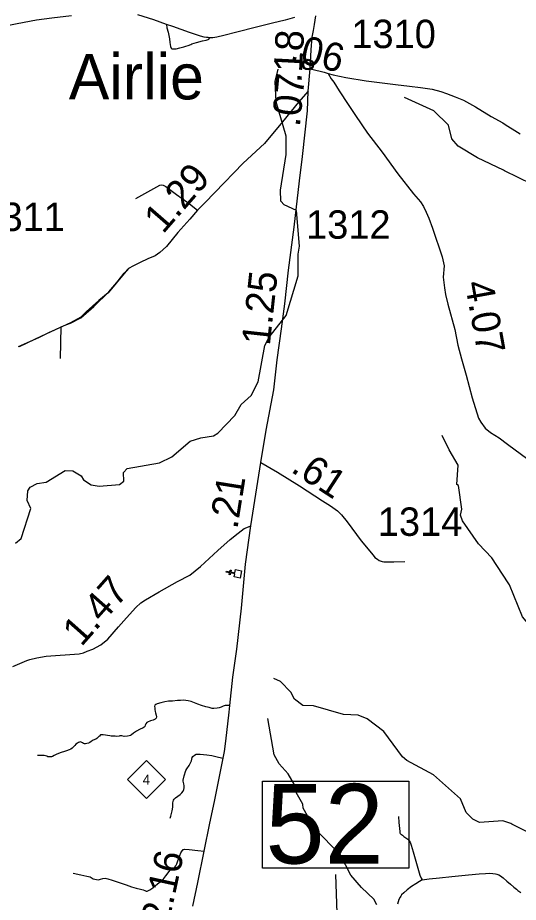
# Model space of a CAD drawing. Extents: x 2290615 to 2522933, y 819489 to 1012715.
# Drawn here: x 2322940 to 2331750, y 928394 to 943964 of the extents above; entities that cross this region are included whole.
import ezdxf

# ---------------------------------------------------------------- set-up
doc = ezdxf.new("R2010")
doc.units = 0
for name, color, linetype in [('Exist Civil Demographics City Label', 7, 'Continuous'), ('Exist Civil Demographics Community CELL', 7, 'Continuous'), ('Exist Cultural Church CELL', 7, 'Continuous'), ('Exist Hydrographic Misc Water Feature', 7, 'Continuous'), ('Exist Road Non-System Type 51', 7, 'Continuous'), ('Exist Road Primary NC Attributed', 7, 'Continuous'), ('Exist Road Primary NC Mileage Hundredths English Label', 7, 'Continuous'), ('Exist Road Primary NC Shield CELL', 7, 'Continuous'), ('Exist Road Primary NC Shield Number Label', 7, 'Continuous'), ('Exist Road Primary NC Structure Standard Bridge Number Label', 7, 'Continuous'), ('Exist Road Secondary Mileage Hundredths English Label', 7, 'Continuous'), ('Exist Road Secondary Type 20 Attributed', 7, 'Continuous'), ('Exist Road Secondary Type 41 Attributed', 7, 'Continuous'), ('Exist Road Secondary Type 51 Attributed', 7, 'Continuous'), ('Exist Road Secondary Type 51 Number Label', 7, 'Continuous')]:
    doc.layers.add(name, color=color, linetype=linetype)

msp = doc.modelspace()

# ---------------------------------------------------------------- linework, layer by layer
at = {"layer": 'Exist Civil Demographics Community CELL'}
msp.add_lwpolyline([(2327972, 943150), (2327973, 943156), (2327975, 943162), (2327978, 943169), (2327981, 943175), (2327984, 943181), (2327988, 943186), (2327992, 943190), (2327996, 943195), (2328002, 943200), (2328007, 943203), (2328012, 943206), (2328017, 943209), (2328023, 943211), (2328028, 943213), (2328033, 943214), (2328037, 943215), (2328042, 943215), (2328048, 943216), (2328052, 943215), (2328058, 943215), (2328063, 943214), (2328068, 943213), (2328073, 943212), (2328078, 943210), (2328085, 943207), (2328091, 943204), (2328096, 943200), (2328101, 943196), (2328104, 943193), (2328109, 943189), (2328112, 943184), (2328116, 943179), (2328119, 943174), (2328121, 943169), (2328123, 943164), (2328125, 943159), (2328126, 943155), (2328127, 943148), (2328128, 943144), (2328128, 943138), (2328128, 943132), (2328127, 943126), (2328126, 943121), (2328125, 943115), (2328123, 943109), (2328120, 943104), (2328117, 943098), (2328114, 943092), (2328111, 943088), (2328106, 943083), (2328101, 943078), (2328096, 943074), (2328091, 943070), (2328087, 943068), (2328080, 943065), (2328073, 943062), (2328067, 943061), (2328060, 943059), (2328056, 943059), (2328051, 943059), (2328046, 943059), (2328041, 943059), (2328036, 943060), (2328030, 943061), (2328025, 943062), (2328020, 943064), (2328016, 943066), (2328012, 943068), (2328005, 943072), (2327999, 943077), (2327994, 943081), (2327990, 943086), (2327987, 943090), (2327984, 943094), (2327980, 943101), (2327978, 943105), (2327976, 943109), (2327974, 943117), (2327972, 943124), (2327971, 943129), (2327971, 943136), (2327971, 943140), (2327971, 943147)], close=True, dxfattribs=at)
for centre, radius in [((2328050, 943138), 94.3), ((2328049, 943138), 76.7)]:
    msp.add_circle(centre, radius, dxfattribs=at)
at = {"layer": 'Exist Cultural Church CELL'}
msp.add_lwpolyline([(2326749, 934122), (2326760, 934178), (2326685, 934192), (2326679, 934161), (2326663, 934164), (2326669, 934195), (2326610, 934207), (2326613, 934223), (2326672, 934211), (2326679, 934242), (2326694, 934239), (2326688, 934208), (2326763, 934193), (2326774, 934250), (2326879, 934230), (2326854, 934101)], close=True, dxfattribs=at)
at = {"layer": 'Exist Hydrographic Misc Water Feature'}
for points in [[(2322900, 934714), (2323000, 934797), (2323169, 935323), (2323109, 935464), (2323116, 935639), (2323157, 935700), (2323281, 935767), (2323439, 935787), (2323778, 935997), (2323912, 935990), (2324054, 935900), (2324096, 935833), (2324231, 935744), (2324373, 935720), (2324731, 935748), (2324805, 935807), (2324803, 935958), (2324869, 936032), (2325434, 936131), (2325650, 936235), (2325972, 936511), (2326163, 936571), (2326387, 936607), (2326462, 936649), (2326759, 936964), (2326873, 937155), (2327046, 937317), (2327169, 937558), (2327287, 938193), (2327368, 938344), (2327664, 938721), (2327873, 939422), (2327878, 939800), (2327901, 939942), (2327844, 940573), (2327627, 940669), (2327568, 940735), (2327565, 940929), (2327667, 941554), (2327664, 941878), (2327491, 942485), (2327470, 942842), (2327526, 943061)], [(2331507, 941268), (2331488, 941278), (2331033, 941498), (2330690, 941704), (2330580, 941834), (2330519, 942075), (2330266, 942324), (2329747, 942558)], [(2334376, 940329), (2333833, 940465), (2333313, 940742), (2333146, 940787), (2332887, 940826), (2332727, 940918), (2332227, 940953), (2331985, 941032), (2331507, 941268)], [(2331594, 933982), (2331571, 934018), (2331284, 934455), (2331048, 934701), (2330769, 935106), (2330734, 935207), (2330758, 935313), (2330695, 935730), (2330670, 935746), (2330692, 936088), (2330531, 936360), (2330411, 936611)], [(2334475, 930033), (2334441, 930065), (2334439, 930242), (2334471, 930282), (2334469, 930483), (2334392, 930630), (2334296, 930997), (2334110, 931229), (2333638, 931679), (2333571, 931778), (2332900, 932105), (2332757, 932254), (2332646, 932476), (2332266, 932847), (2332215, 932996), (2332121, 933127), (2331978, 933236), (2331826, 933417), (2331594, 933982)], [(2331637, 929772), (2331619, 929779), (2331475, 929831), (2331067, 929801), (2330950, 929859), (2330832, 929975), (2330730, 930214), (2330259, 930635), (2329789, 930888), (2329714, 930953), (2329384, 931399), (2329090, 931624), (2328931, 931686), (2328673, 931702), (2328146, 931854), (2327955, 931859), (2327812, 931968), (2327744, 932090), (2327567, 932280), (2327450, 932331)], [(2329258, 928352), (2329207, 928448), (2328989, 928656), (2328803, 928871), (2328616, 929234), (2328170, 929689), (2327966, 930051), (2327957, 930120), (2327838, 930325), (2327803, 930474), (2327701, 930657), (2327541, 930831), (2327456, 930989), (2327341, 931627)], [(2333816, 928683), (2333772, 928875), (2333712, 928974), (2333595, 929071), (2333218, 929233), (2333041, 929400), (2332856, 929504), (2331905, 929635), (2331637, 929772)]]:
    msp.add_lwpolyline(points, dxfattribs=at)
at = {"layer": 'Exist Road Non-System Type 51'}
msp.add_line((2323691, 937966), (2323707, 938526), dxfattribs=at)
msp.add_line((2323691, 937966), (2323707, 938526), dxfattribs=at)
for points in [[(2325561, 943844), (2325563, 943783), (2325587, 943708), (2325612, 943595), (2325617, 943526), (2325630, 943459), (2325640, 943429), (2325651, 943417), (2325674, 943415), (2325729, 943419), (2325793, 943433), (2325863, 943452), (2325899, 943464), (2325942, 943475), (2325986, 943492), (2326003, 943502), (2326089, 943528), (2326190, 943555), (2326257, 943568), (2326290, 943579), (2326306, 943589), (2326321, 943608)], [(2325561, 943844), (2325563, 943783), (2325587, 943708), (2325612, 943595), (2325617, 943526), (2325630, 943459), (2325640, 943429), (2325651, 943417), (2325674, 943415), (2325729, 943419), (2325793, 943433), (2325863, 943452), (2325899, 943464), (2325942, 943475), (2325986, 943492), (2326003, 943502), (2326089, 943528), (2326190, 943555), (2326257, 943568), (2326290, 943579), (2326306, 943589), (2326321, 943608)], [(2325018, 940784), (2325439, 941014), (2325467, 941022), (2325499, 941019), (2325546, 940991), (2325733, 940853), (2325932, 940713), (2326104, 940576)], [(2325018, 940784), (2325439, 941014), (2325467, 941022), (2325499, 941019), (2325546, 940991), (2325733, 940853), (2325932, 940713), (2326104, 940576)], [(2323707, 938526), (2323784, 938556), (2323871, 938588), (2324049, 938680), (2324282, 938881), (2324542, 939137), (2324684, 939303), (2324815, 939470), (2324890, 939549)], [(2323707, 938526), (2323784, 938556), (2323871, 938588), (2324049, 938680), (2324282, 938881), (2324542, 939137), (2324684, 939303), (2324815, 939470), (2324890, 939549)], [(2322955, 938178), (2323312, 938337), (2323501, 938429), (2323593, 938471), (2323707, 938526)], [(2322955, 938178), (2323312, 938337), (2323501, 938429), (2323593, 938471), (2323707, 938526)], [(2326673, 931860), (2326619, 931860), (2326588, 931859), (2326555, 931846), (2326523, 931830), (2326487, 931819), (2326450, 931809), (2326394, 931805), (2326361, 931807), (2326312, 931821), (2326250, 931834), (2326174, 931857), (2326110, 931882), (2325990, 931930), (2325940, 931939), (2325899, 931946), (2325851, 931950), (2325803, 931948), (2325750, 931946), (2325664, 931937), (2325595, 931932), (2325531, 931921), (2325456, 931905), (2325394, 931887), (2325369, 931875), (2325355, 931862), (2325348, 931841), (2325351, 931819), (2325353, 931786), (2325357, 931754), (2325365, 931732), (2325378, 931691), (2325383, 931659), (2325376, 931634), (2325358, 931620), (2325323, 931602), (2325278, 931591), (2325226, 931567), (2325210, 931558), (2325193, 931534), (2325185, 931511), (2325175, 931490), (2325164, 931477), (2325145, 931467), (2325084, 931438), (2325031, 931406), (2324979, 931371), (2324945, 931342), (2324924, 931332), (2324903, 931327), (2324874, 931320), (2324813, 931315), (2324774, 931324), (2324740, 931324), (2324724, 931317), (2324687, 931314), (2324655, 931316), (2324642, 931317), (2324614, 931317), (2324595, 931319), (2324585, 931321), (2324559, 931324), (2324520, 931333), (2324482, 931338), (2324441, 931340), (2324416, 931344), (2324399, 931342), (2324390, 931335), (2324377, 931321), (2324368, 931312), (2324354, 931299), (2324341, 931286), (2324333, 931278), (2324314, 931268), (2324269, 931249), (2324235, 931226), (2324210, 931207), (2324183, 931198), (2324158, 931187), (2324133, 931184), (2324113, 931185), (2324096, 931192), (2324082, 931200), (2324070, 931207), (2324056, 931214), (2324044, 931217), (2324029, 931215), (2324012, 931207), (2323993, 931194), (2323964, 931176), (2323943, 931156), (2323922, 931132), (2323910, 931118), (2323899, 931105), (2323877, 931088), (2323848, 931077), (2323801, 931062), (2323761, 931048), (2323704, 931032), (2323659, 931014)], [(2323659, 931014), (2323619, 930994), (2323583, 930976), (2323555, 930961), (2323532, 930955), (2323510, 930953), (2323497, 930953), (2323472, 930955), (2323450, 930966), (2323431, 930973), (2323404, 930979), (2323378, 930981), (2323353, 930981), (2323291, 930980)], [(2325625, 929876), (2325635, 929908), (2325660, 930005), (2325667, 930067), (2325668, 930121), (2325672, 930145), (2325674, 930167), (2325684, 930193), (2325694, 930211), (2325715, 930233), (2325755, 930261), (2325797, 930290), (2325830, 930322), (2325854, 930351), (2325864, 930381), (2325867, 930412), (2325867, 930446), (2325861, 930480), (2325852, 930526), (2325854, 930544), (2325871, 930623), (2325897, 930717), (2325915, 930744), (2325957, 930801), (2325997, 930883), (2326008, 930942), (2326020, 930960), (2326051, 930985), (2326079, 930999), (2326115, 931003), (2326153, 931000), (2326266, 930987), (2326359, 930976), (2326471, 930951), (2326558, 930934)], [(2329639, 929907), (2329650, 929797), (2329656, 929692), (2329663, 929641), (2329667, 929615), (2329671, 929605), (2329680, 929596), (2329693, 929585), (2329710, 929575), (2329737, 929554), (2329769, 929528), (2329803, 929505), (2329822, 929485), (2329846, 929451), (2329867, 929400), (2329897, 929285), (2329944, 929119), (2329980, 928993), (2330018, 928874), (2330040, 928822), (2330057, 928790)], [(2323916, 928906), (2324049, 928877), (2324155, 928855), (2324216, 928840), (2324270, 928805), (2324325, 928793), (2324359, 928791), (2324398, 928799), (2324439, 928815), (2324479, 928817), (2324526, 928808), (2324605, 928783), (2324707, 928748), (2324850, 928702), (2324943, 928669), (2325027, 928645), (2325102, 928623), (2325148, 928611), (2325177, 928600), (2325203, 928592), (2325217, 928592), (2325268, 928612), (2325320, 928651), (2325400, 928719), (2325469, 928772), (2325513, 928814), (2325544, 928859), (2325568, 928889), (2325599, 928933), (2325630, 928968), (2325665, 928988), (2325692, 929001), (2325705, 929012), (2325720, 929034), (2325740, 929071), (2325760, 929122), (2325793, 929221), (2325813, 929263), (2325835, 929299), (2325853, 929321), (2325862, 929325), (2325880, 929331), (2325958, 929321), (2326111, 929306), (2326223, 929297)], [(2323916, 928906), (2324049, 928877), (2324155, 928855), (2324216, 928840), (2324270, 928805), (2324325, 928793), (2324359, 928791), (2324398, 928799), (2324439, 928815), (2324479, 928817), (2324526, 928808), (2324605, 928783), (2324707, 928748), (2324850, 928702), (2324943, 928669), (2325027, 928645), (2325102, 928623), (2325148, 928611), (2325177, 928600), (2325203, 928592), (2325217, 928592), (2325268, 928612), (2325320, 928651), (2325400, 928719), (2325469, 928772), (2325513, 928814), (2325544, 928859), (2325568, 928889), (2325599, 928933), (2325630, 928968), (2325665, 928988), (2325692, 929001), (2325705, 929012), (2325720, 929034), (2325740, 929071), (2325760, 929122), (2325793, 929221), (2325813, 929263), (2325835, 929299), (2325853, 929321), (2325862, 929325), (2325880, 929331), (2325958, 929321), (2326111, 929306), (2326223, 929297)], [(2330057, 928790), (2330010, 928761), (2329944, 928722), (2329871, 928671), (2329795, 928611), (2329733, 928562), (2329695, 928526), (2329682, 928505), (2329669, 928484), (2329648, 928445), (2329622, 928360)], [(2330057, 928790), (2330097, 928798), (2330182, 928809), (2330364, 928826), (2330579, 928847), (2330871, 928879), (2331058, 928896), (2331171, 928902), (2331250, 928909), (2331299, 928904), (2331348, 928898), (2331371, 928892), (2331405, 928879), (2331439, 928858), (2331484, 928826), (2331546, 928768), (2331610, 928713), (2331672, 928659), (2331716, 928625), (2331742, 928604), (2331792, 928568)]]:
    msp.add_lwpolyline(points, dxfattribs=at)
at = {"layer": 'Exist Road Primary NC Attributed'}
for p, q in [((2328049, 942672), (2328089, 943065)), ((2327042, 935022), (2327220, 936138))]:
    msp.add_line(p, q, dxfattribs=at)
for points in [[(2328089, 943065), (2328106, 943398), (2328124, 943624), (2328145, 943740), (2328164, 943844), (2328186, 944000)], [(2327220, 936138), (2327310, 936705), (2327446, 937413), (2327508, 937942), (2327585, 938489), (2327640, 938926), (2327704, 939520), (2327804, 940277), (2327900, 941095), (2327950, 941522), (2328039, 942325), (2328049, 942672)], [(2326021, 928328), (2326107, 928743), (2326223, 929297), (2326319, 929790), (2326402, 930169), (2326558, 930934), (2326577, 931047), (2326600, 931232), (2326661, 931741), (2326673, 931860), (2326725, 932357), (2326795, 932848), (2326880, 933573), (2326951, 934343), (2327042, 935022)]]:
    msp.add_lwpolyline(points, dxfattribs=at)
at = {"layer": 'Exist Road Primary NC Shield CELL'}
msp.add_lwpolyline([(2324875, 930556), (2325208, 930889), (2325541, 930556), (2325208, 930223)], close=True, dxfattribs=at)
at = {"layer": 'Exist Road Primary NC Structure Standard Bridge Number Label'}
msp.add_line((2328754, 922140), (2328538, 928881), dxfattribs=at)
msp.add_lwpolyline([(2327249, 930527), (2329826, 930527), (2329826, 928998), (2327249, 928998)], close=True, dxfattribs=at)
at = {"layer": 'Exist Road Secondary Type 20 Attributed'}
for points in [[(2323889, 943995), (2323539, 943958), (2323271, 943918), (2323055, 943878), (2322722, 943818), (2322473, 943773), (2322346, 943742), (2322238, 943699), (2321989, 943589), (2321200, 943518), (2320651, 943644)], [(2327811, 943965), (2327646, 943922), (2327425, 943868), (2327144, 943798), (2326798, 943710), (2326569, 943651), (2326442, 943621), (2326371, 943611), (2326321, 943608), (2326291, 943614), (2326263, 943615), (2326223, 943623), (2326155, 943641), (2325965, 943704), (2325667, 943807), (2325561, 943844), (2325334, 943927), (2325055, 944014)], [(2328049, 942672), (2327881, 942479), (2327597, 942131), (2327286, 941748), (2326908, 941403), (2326407, 940889), (2326235, 940707), (2326104, 940576), (2325970, 940421), (2325759, 940185), (2325558, 939939), (2325443, 939830), (2325359, 939773), (2325230, 939718), (2325093, 939656), (2324977, 939597), (2324890, 939549), (2324813, 939459), (2324670, 939294), (2324532, 939121), (2324370, 938986), (2324145, 938787), (2324048, 938694), (2323871, 938592), (2323665, 938502), (2323358, 938356), (2322968, 938172)]]:
    msp.add_lwpolyline(points, dxfattribs=at)
at = {"layer": 'Exist Road Secondary Type 41 Attributed'}
msp.add_lwpolyline([(2328404, 942985), (2328459, 942889), (2328504, 942829), (2328596, 942677), (2328757, 942439), (2328882, 942243), (2329098, 941930), (2329351, 941598), (2329631, 941218), (2329903, 940867), (2330027, 940726), (2330080, 940644), (2330131, 940541), (2330174, 940435), (2330238, 940260), (2330409, 939756), (2330446, 939597), (2330428, 939399), (2330449, 939207), (2330468, 939093), (2330510, 938921), (2330635, 938477), (2330685, 938199), (2330748, 937961), (2330830, 937670), (2330938, 937275), (2331050, 936913), (2331088, 936848), (2331167, 936741), (2331258, 936666), (2331411, 936569), (2331558, 936456), (2331919, 936194)], dxfattribs=at)
at = {"layer": 'Exist Road Secondary Type 51 Attributed'}
for points in [[(2328089, 943065), (2328263, 943023), (2328332, 943005), (2328404, 942985)], [(2328404, 942985), (2328494, 942958), (2328712, 942911), (2329070, 942851), (2329589, 942789), (2329837, 942762), (2330028, 942737), (2330232, 942705), (2330386, 942665), (2330486, 942630), (2330637, 942573), (2330783, 942511), (2330994, 942395), (2331274, 942228), (2331477, 942115), (2331536, 942074), (2331641, 942009), (2331782, 941919)], [(2327220, 936138), (2327509, 935964), (2327901, 935723), (2328302, 935462), (2328446, 935371), (2328565, 935285), (2328639, 935217), (2328737, 935093), (2328987, 934759), (2329195, 934502), (2329227, 934465), (2329270, 934432), (2329301, 934412), (2329354, 934394), (2329384, 934389), (2329442, 934388), (2329560, 934388), (2329753, 934394)], [(2322853, 932543), (2323101, 932652), (2323156, 932670), (2323279, 932700), (2323441, 932726), (2324019, 932770), (2324097, 932788), (2324162, 932814), (2324264, 932852), (2324404, 932924), (2324524, 933023), (2324716, 933245), (2324856, 933403), (2325018, 933581), (2325105, 933666), (2325188, 933718), (2325432, 933858), (2325753, 934038), (2325967, 934150), (2326158, 934304), (2326461, 934588), (2326678, 934782), (2326819, 934894), (2326926, 934971), (2326999, 935005), (2327042, 935022)]]:
    msp.add_lwpolyline(points, dxfattribs=at)

# ---------------------------------------------------------------- texts
at = {"layer": 'Exist Civil Demographics City Label'}
msp.add_text('Airlie', height=800, rotation=360, dxfattribs=at).set_placement((2323839, 942527))
at = {"layer": 'Exist Road Primary NC Mileage Hundredths English Label'}
for s, rotation, p in [('.18', 87.0118, (2327933, 942809)), ('.07', 84.2219, (2327903, 942031)), ('1.25', 83.796, (2327376, 938183)), ('.21', 80.9445, (2326804, 934950)), ('2.16', 77.7633, (2325591, 927970))]:
    msp.add_text(s, height=500, rotation=rotation, dxfattribs=at).set_placement(p)
at = {"layer": 'Exist Road Primary NC Shield Number Label'}
msp.add_text('4', height=175, dxfattribs=at).set_placement((2325140, 930466))
at = {"layer": 'Exist Road Primary NC Structure Standard Bridge Number Label'}
msp.add_text('52', height=1400, dxfattribs=at).set_placement((2327300, 929077))
at = {"layer": 'Exist Road Secondary Mileage Hundredths English Label'}
for s, rotation, p in [('.06', 345.9541, (2327709, 943218)), ('1.29', 48.9662, (2325497, 940144)), ('4.07', 280.1852, (2330806, 939296)), ('.61', 326.995, (2327727, 935983)), ('1.47', 48.4492, (2324060, 932880))]:
    msp.add_text(s, height=500, rotation=rotation, dxfattribs=at).set_placement(p)
at = {"layer": 'Exist Road Secondary Type 51 Number Label'}
for s, p in [('1310', (2328811, 943429)), ('1311', (2322283, 940210)), ('1314', (2329277, 934844))]:
    msp.add_text(s, height=500, rotation=360, dxfattribs=at).set_placement(p)
msp.add_text('1312', height=500, dxfattribs=at).set_placement((2328014, 940074))

doc.saveas('drawing.dxf')
